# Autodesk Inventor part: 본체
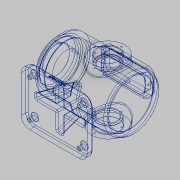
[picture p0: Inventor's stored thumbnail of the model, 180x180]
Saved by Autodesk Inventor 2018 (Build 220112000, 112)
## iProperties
Created: 2021-11
Part Number: 본체
Material: 알루미늄 6061
Document SubType Name: Modeling
Designer: home
Density: 2.7 g/cm^3
Appearance: 알루미늄 - 평지
Mass: 3539.16 g
Surface Area: 2411.25 cm^2
Volume: 1310.8 cm^3
Author: home
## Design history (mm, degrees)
sketch "스케치1"
  geometry: L1 (-117, 65)-(0, 65); L2 (0, 65)-(58.993, 65); L3 (0, 65)-(58.993, 65); L4 (-117, 47.5)-(-117, 65); L5 (-117, 0)-(83, 0); L6 (-21, 0)-(21, 0); L7 (-102, 55)-(54.239, 55); L8 (83, 0)-(-127, 0); L9 (-127, 32.5)-(-127, 47.5); L10 (-127, 47.5)-(-117, 47.5); L11 (-127, 0)-(-102, 0); L12 (-102, 32.5)-(-127, 32.5); L13 (-102, 32.5)-(-102, 55); A1 r 21 centre (0, 0) between (21, 0) and (-21, 0); A2 r 100 centre (-17, 0) between (83, 0) and (58.993, 65); A3 r 90 centre (-17, 0) between (73, 0) and (54.239, 55); 3 further points
  constraints: 26 end point, 6 point on circle, 4 horizontal, 3 centre point, 3 point on line, 2 perpendicular, 2 vertical, 1 coincident, 1 collinear, 1 parallel, 1 tangent
  dimensions: "d0" = 42 diameter of A1; "d11" = 100 radius of A2; "d12" = 83 distance of L5.end point (0, 0); "d16" = 65 distance between parallel lines of L6 L3; "d17" = 65 distance between parallel lines of L3 L5; "d18" = 65 distance from line of point (0, 0) L2; "d20" = 0 distance from line of point (83, 65) L2; "d21" = 200 distance from line of point (83, 65) L4; "d22" = 117 distance from line of L1.end L4; "d24" = 10 radial gap between concentric circles of A2 A3; "d29" = 10 distance between parallel lines of L7 L3; "d30" = 32.5 distance between parallel lines of L12 L3; "d31" = 17.5 distance between parallel lines of L10 L3; "d206" = 25 distance of L12.start L9.start; "d207" = 15 distance between parallel lines of L13 L4; "d208" = 102 distance from line of point (0, 0) L13; "d209" = 0 distance from line of L11.end L13; "d210" = 5 distance from line of point (-107, 32.5) L13; "d211" = 15 distance from line of L5.start L13; "d212" = 25 distance from line of L8.end L13
revolve "회전1" sketch "스케치1" stored, may be unused: angle "d23" = 90 deg
node "작업 평면1"
sketch "스케치2"
  geometry: L1 (77, 15)-(77, -15); L2 (-43, 15)-(-43, -15); L3 (62, -30)-(-28, -30); L4 (62, 30)-(-28, 30); A1 r 15 centre (62, -15) between (62, -30) and (77, -15); A2 r 15 centre (62, 15) between (77, 15) and (62, 30); A3 r 15 centre (-28, 15) between (-28, 30) and (-43, 15); A4 r 15 centre (-28, -15) between (-43, -15) and (-28, -30); 1 further point
  constraints: 10 tangent, 8 end point, 8 point on circle, 4 centre point, 3 equal radius, 1 horizontal, 1 parallel, 1 vertical
  dimensions: "d39" = 120 distance between parallel lines of L1 L2; "d44" = 15 radius of A1; "d45" = 77 distance from line of point (0, 0) L1; "d46" = 30 distance from line of point (0, 0) L4
extrude "돌출1" join sketch "스케치2" stored distance "d47" = 10; taper "d48" = 0 deg
node "작업 평면2"
sketch "스케치3"
  geometry: C1 r 40 at (0, 0); 1 further point
  constraints: 1 centre point, 1 coincident
  dimensions: "d55" = 80 diameter of C1
extrude "돌출2" join sketch "스케치3" stored distance "d56" = 10; taper "d57" = 0 deg
hole "구멍1" diameter "d60" = 42; stored, may be unused: countersink angle "d64" = 90 deg, drill point angle "d66" = 0 deg; dims "d58" = 10, "d59" = 10, "d61" = 6, "d62" = 52, "d63" = 18, "d65" = 60
node "작업 평면3"
sketch "스케치5"
  geometry: L1 (97, 45)-(97, -45); L2 (-63, 45)-(-63, -45); L3 (77, -65)-(-43, -65); L4 (77, 65)-(-43, 65); A1 r 20 centre (77, -45) between (77, -65) and (97, -45); A2 r 20 centre (-43, -45) between (-63, -45) and (-43, -65); A3 r 20 centre (-43, 45) between (-43, 65) and (-63, 45); A4 r 20 centre (77, 45) between (97, 45) and (77, 65); 4 further points
  constraints: 8 end point, 8 point on circle, 8 tangent, 6 point on line, 4 centre point, 3 equal radius, 2 parallel, 1 horizontal, 1 vertical
  dimensions: "d73" = 160 distance of point (97, -65) point (-63, -65); "d74" = 130 distance of point (97, 65) point (97, -65); "d76" = 20 radius of A1; "d77" = 97 distance from line of point (0, 0) L1; "d78" = 65 distance from line of point (0, 0) L4
extrude "돌출3" join sketch "스케치5" distance "d79" = 14; taper "d80" = 0 deg
sketch "스케치7"
  geometry: L1 (43, -100)-(-77, -100) reference; L2 (43, -100)-(26.985, -56); L3 (-77, -100)-(-60.985, -56); L4 (-77, -100)-(-23.285, -100); L5 (-60.985, -56)-(26.985, -56); L6 (-77, -100)-(43, -100); 1 further point
  constraints: 10 end point, 1 collinear, 1 horizontal, 1 parallel
  dimensions: "d96" = 70 deg angle of L4 L3; "d97" = 70 deg angle of L2 L1; "d98" = 44 distance between parallel lines of L5 L1; "d99" = 62.28725 distance from line of L4.end L2
extrude "돌출5" join sketch "스케치7" stored distance "d100" = 14; taper "d101" = 0 deg
sketch "스케치9"
  geometry: L1 (40.41, 9.298)-(81.889, 9.298); L2 (81.889, 9.298)-(81.889, 3.294); L3 (81.889, 3.294)-(40.41, 3.294); L4 (40.41, 3.294)-(40.41, 9.298); 1 further point
  constraints: 1 horizontal, 2 other
  dimensions: "d113" = 41.47897 distance between parallel lines of L4 L2; "d114" = 6.00407 distance between parallel lines of L1 L3; "d115" = 4.88899 distance from line of point (77, 114) L2; "d116" = 104.7016 distance from line of point (77, 114) L1
feature "엠보싱1" sketch "스케치9" dims "d0" = 42, "d11" = 100, "d12" = 83, "d16" = 65, "d17" = 65, "d18" = 65, "d20" = 0, "d21" = 200, "d22" = 117, "d24" = 10, "d29" = 10, "d30" = 32.5, "d31" = 17.5, "d117" = 0.5, "d118" = 0, "d206" = 25, "d207" = 15, "d208" = 102, "d209" = 0, "d210" = 5, "d211" = 15, "d212" = 25
sketch "스케치10"
  geometry: L1 (-77, -65)-(43, -65) reference; L2 (-97, 45)-(-97, -45) reference; L3 (43, 65)-(-77, 65) reference; L4 (63, -45)-(63, 45) reference; A1 r 20 centre (-77, 45) between (-77, 65) and (-97, 45) reference; A2 r 20 centre (-77, -45) between (-97, -45) and (-77, -65) reference; A3 r 20 centre (-77, 45) between (-77, 65) and (-97, 45) reference; A4 r 20 centre (43, 45) between (63, 45) and (43, 65) reference; A5 r 20 centre (43, -45) between (43, -65) and (63, -45) reference; A6 r 20 centre (-77, -45) between (-97, -45) and (-77, -65) reference; 4 further points
  constraints: 4 coincident
hole "구멍2" sketch "스케치10" at (-77, 45), (43, 45), (43, -45), (-77, -45) diameter "d129" = 9; stored, may be unused: countersink angle "d133" = 90 deg, drill point angle "d135" = 0 deg; dims "d130" = 6, "d131" = 18, "d132" = 2, "d134" = 14
node "작업 평면5"
sketch "스케치11"
  geometry: L1 (110, 0)-(110, 14) reference; L2 (-5, 14)-(12.476, 62.015); L3 (-5, 14)-(46.096, 14); 1 further point
  constraints: 4 end point, 1 equal length, 1 horizontal
  dimensions: "d138" = 70 deg angle of L3 L2; "d139" = 0 distance from line of L1.end L3; "d140" = 108.06465 distance from line of L1.end L2; "d141" = 63.90366 distance from line of L3.end L1
feature "리브2" sketch "스케치11" dims "d142" = 1, "d143" = 14, "d144" = 0, "d145" = 0, "d146" = 1, "d147" = 1
sketch "스케치12"
  geometry: 5 further points
  dimensions: "d149" = 32.5 distance of point (0, 0) point (32.5, 0); "d150" = 32.5 distance of point (0, 0) point (0, 32.5); "d151" = 32.5 distance of point (0, 0) point (0, -32.5); "d152" = 32.5 distance of point (0, 0) point (-32.5, 0); "d153" = 45.96194 distance of point (32.5, 0) point (0, 32.5); "d154" = 45.96194 distance of point (32.5, 0) point (0, -32.5); "d155" = 65 distance of point (32.5, 0) point (-32.5, 0); "d156" = 32.5 horizontal distance of point (32.5, 0) point (0, 32.5)
hole "구멍3" sketch "스케치12" at (0, 32.5), (-32.5, 0), (0, -32.5), (32.5, 0) diameter "d157" = 3.242; stored, may be unused: countersink angle "d161" = 90 deg, drill point angle "d163" = 118 deg; dims "d158" = 11, "d159" = 18, "d160" = 2, "d162" = 13
sketch "스케치13"
  geometry: 5 further points
  dimensions: "d165" = 40 distance of point (0, 0) point (40, 0); "d166" = 40 distance of point (0, 0) point (0, 40); "d167" = 40 distance of point (0, 0) point (0, -40); "d168" = 40 distance of point (0, 0) point (-40, 0); "d169" = 56.56854 distance of point (40, 0) point (0, 40); "d170" = 56.56854 distance of point (40, 0) point (0, -40); "d171" = 80 distance of point (40, 0) point (-40, 0); "d172" = 40 horizontal distance of point (40, 0) point (0, 40)
hole "구멍4" sketch "스케치13" at (0, 40), (40, 0), (0, -40), (-40, 0) diameter "d173" = 3.242; stored, may be unused: countersink angle "d177" = 90 deg, drill point angle "d179" = 118 deg; dims "d174" = 11, "d175" = 18, "d176" = 2, "d178" = 13
sketch "스케치14"
  geometry: L1 (28, 30)-(-62, 30) reference; L2 (-62, -30)-(28, -30) reference; L3 (43, -15)-(43, 15) reference; L4 (28, 30)-(-62, 30) reference; L5 (-77, 15)-(-77, -15) reference; L6 (33, 15)-(33, -15); L7 (28, -20)-(-62, -20); L8 (-67, -15)-(-67, 15); L9 (-62, 20)-(28, 20); A1 r 15 centre (28, -15) between (28, -30) and (43, -15) reference; A2 r 15 centre (28, 15) between (43, 15) and (28, 30) reference; A3 r 15 centre (-62, 15) between (-62, 30) and (-77, 15) reference; A4 r 15 centre (-62, -15) between (-77, -15) and (-62, -30) reference; A5 r 5 centre (28, -15) between (28, -20) and (33, -15); A6 r 5 centre (-62, -15) between (-67, -15) and (-62, -20); A7 r 5 centre (-62, 15) between (-62, 20) and (-67, 15); A8 r 5 centre (28, 15) between (33, 15) and (28, 20); 1 further point
  constraints: 8 end point, 8 point on circle, 4 centre point, 7 other
  dimensions: "d180" = 10 distance between parallel lines of L3 L6
extrude "돌출6" cut sketch "스케치14" distance "d181" = 50; taper "d182" = 0 deg
sketch "스케치15"
  geometry: L1 (33, 15)-(33, -15) reference; L2 (28, -20)-(-62, -20) reference; L3 (-67, -15)-(-67, 15) reference; L4 (-62, 20)-(28, 20) reference; L5 (-62, -30)-(28, -30) reference; L6 (43, -15)-(43, 15) reference; L7 (28, 30)-(-62, 30) reference; L8 (-77, 15)-(-77, -15) reference; A1 r 5 centre (28, 15) between (33, 15) and (28, 20) reference; A2 r 5 centre (28, -15) between (28, -20) and (33, -15) reference; A3 r 5 centre (-62, -15) between (-67, -15) and (-62, -20) reference; A4 r 5 centre (-62, 15) between (-62, 20) and (-67, 15) reference; A5 r 15 centre (28, -15) between (28, -30) and (43, -15) reference; A6 r 15 centre (28, 15) between (43, 15) and (28, 30) reference; A7 r 15 centre (-62, 15) between (-62, 30) and (-77, 15) reference; A8 r 15 centre (-62, -15) between (-77, -15) and (-62, -30) reference; 5 further points
  dimensions: "d184" = 5 distance from line of point (38, 0) L6; "d185" = 30 distance from line of point (38, 0) L7; "d186" = 60 distance from line of point (-17, 25) L6; "d187" = 5 distance from line of point (-17, 25) L7; "d188" = 60 distance from line of point (-17, -25) L6; "d189" = 55 distance from line of point (-17, -25) L7; "d190" = 115 distance from line of point (-72, 0) L6; "d191" = 30 distance from line of point (-72, 0) L7
hole "구멍5" sketch "스케치15" at (-17, 25), (-72, 0), (-17, -25), (38, 0) diameter "d192" = 3.242; stored, may be unused: countersink angle "d196" = 90 deg, drill point angle "d198" = 118 deg; dims "d193" = 9, "d194" = 18, "d195" = 2, "d197" = 11
chamfer "모따기1" distance "d199" = 1; stored, may be unused: second distance "d200" = 2, angle "d201" = 45 deg
fillet "모깎기1" dims "d202" = 0.3
fillet "모깎기2" dims "d203" = 3
fillet "모깎기3" dims "d204" = 3
fillet "모깎기4" dims "d205" = 10
fillet "모깎기5" dims "d213" = 3
fillet "모깎기6" dims "d214" = 3
node "솔리드1"
mirror "미러1"
mirror "미러3"
mirror "미러4"
node "투영된 루프2"
node "투영된 루프3"
node "투영된 루프4"
other parameters: "d49" = 75, "d67" = -114
